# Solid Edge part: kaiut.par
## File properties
Author: Cymax
Template: Normal.par
Last saved by: Cymax
Revision: 24
Application: Solid Edge
Accuracy: 0,990
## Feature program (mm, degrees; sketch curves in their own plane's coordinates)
sketch for "unnamed Protrusion 1" plane through (0, 0, 0) normal (1, 0, 0) x-axis (0, 1, 0)
  arc centre (0, 1288.5152) radius 1839.926 from (-720.5308, -404.4594) to (720.5308, -404.4594) ccw
  line (720.5308, 0) -> (720.5308, -404.4594)
  line (-720.5308, 0) -> (720.5308, 0)
  line (-720.5308, -404.4594) -> (-720.5308, 0)
extrude "unnamed Protrusion 1" add finite 3507.3272 symmetric
sketch for "ExtrudedCutout_7" plane through (0, 0, 0) normal (0, 0, 1) x-axis (1, 0, 0)
  circle centre (-1600, 600) radius 75
extrude "ExtrudedCutout_7" cut finite 100 along -normal
mirror "unnamed Mirror 1" of "ExtrudedCutout_7" about plane through (0, 0, 0) normal (1, 0, 0)
extrude "unnamed Cutout 1" cut finite 100
mirror "unnamed Mirror 2" of "ExtrudedCutout_7", "unnamed Mirror 1" about plane through (0, 0, 0) normal (0, -1, 0)
extrude "unnamed Cutout 2" cut finite 100
extrude "unnamed Cutout 3" cut finite 100
draft "Draft_3"  Angles1 = 10 deg
thinwall "Thinwall_9"  Thickness = 100 mm
sketch for "ExtrudedCutout_12" plane through (-1618.0774, 0, -193.0702) normal (0.984808, 0, 0.173648) x-axis (0, 1, 0)
  line (-185, 196.0486) -> (-185, 1.9564)
  arc centre (-0.7454, 124.9335) radius 221.5245 from (-185, 1.9564) to (185, 4.22) ccw
  line (185, 4.22) -> (185, 196.0486)
extrude "ExtrudedCutout_12" cut finite 276.7398 along -normal
sketch for "unnamed RevolvedCutout 1" #1 plane through (0, -682.1712, -217.5478) normal (0, -0.984808, -0.173648) x-axis (-1, 0, 0)
  arc centre (-1165.304, -97.898) radius 200 from (-1165.304, 102.102) to (-965.304, -97.898) cw
  line (-965.304, -97.898) -> (-965.304, -138.606)
  line (-965.304, -138.606) -> (-1415.304, -138.606)
  line (-1415.304, -138.606) -> (-1415.304, -97.898)
  arc centre (-1215.304, -97.898) radius 200 from (-1215.304, 102.102) to (-1415.304, -97.898) ccw
  line (-1215.304, 102.102) -> (-1165.304, 102.102)
sketch for "unnamed RevolvedCutout 1" #2 plane through (0, -682.1712, -217.5478) normal (0, -0.984808, -0.173648) x-axis (-1, 0, 0)
  line (-515.304, 102.102) -> (-465.304, 102.102)
  arc centre (-465.304, -97.898) radius 200 from (-265.304, -97.898) to (-465.304, 102.102) ccw
  line (-265.304, -97.898) -> (-265.304, -145.2967)
  line (-265.304, -145.2967) -> (-715.304, -145.2967)
  line (-715.304, -145.2967) -> (-715.304, -97.898)
  arc centre (-515.304, -97.898) radius 200 from (-715.304, -97.898) to (-515.304, 102.102) cw
revolve "unnamed RevolvedCutout 1" cut finite
mirror "unnamed Mirror 3" of "unnamed RevolvedCutout 1" about plane through (0, 0, 0) normal (1, 0, 0)
revolve "unnamed RevolvedCutout 2" cut finite 14 deg
mirror "unnamed Mirror 4" of "unnamed Mirror 3", "unnamed RevolvedCutout 1" about plane through (0, 0, 0) normal (0, -1, 0)
revolve "unnamed RevolvedCutout 3" cut finite 14 deg
revolve "unnamed RevolvedCutout 4" cut finite 14 deg
sketch for "ExtrudedCutout_13" plane through (0, 0, 0) normal (0, 0, 1) x-axis (1, 0, 0)
  circle centre (424.9793, 0) radius 75
extrude "ExtrudedCutout_13" cut finite 1310.2189 along -normal
cool vent "Vent_3"  RibThickness = 15 mm; RibDepth = 10 mm; RibExtend = 20 mm; SparThickness = 15 mm; SparOffset = 30 mm; SparDepth = 10 mm; SparExtend = 20 mm
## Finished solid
Body 1: solid body, 112 faces, 331 edges, 214 vertices.
  Faces by surface: plane 66, cylinder 30, torus 16
  Edges by curve: line 199, circle 102, intersection 18, ellipse 12
Bounding box of the edges (mm; curved faces can reach further): 3507.327 x 1441.062 x 551.411, from (-1753.6636, -720.5308, -551.4108) to (1753.6636, 720.5308, 0).
Cylindrical faces by radius (mm): R75 x5, R76.8306 x2, R175 x4, R221.5245 x1, R430.6294 x4, R437.3201 x4, R678.028 x8, R1739.926 x1, R1839.926 x1
Toroidal faces (ring radius, tube radius in mm): R478.028 r200 x16
Planar faces by outward normal: +x 12, +y 1, +z 5, -x 12, -y 1, -z 4, oblique 31
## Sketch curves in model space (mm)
line (1415.304, -782.1798, 349.6287) -> (265.304, -782.1798, 349.6287)
arc centre (1165.304, -699.1711, -121.1371) radius 200 from (1165.304, -664.4414, -318.0986) through (1019.8293, -675.3381, -256.3003) to (965.304, -699.1711, -121.1371)
line (965.304, -699.1711, -121.1371) -> (965.304, -706.2399, -81.0475)
line (965.304, -706.2399, -81.0475) -> (1415.304, -706.2399, -81.0475)
line (1415.304, -706.2399, -81.0475) -> (1415.304, -699.1711, -121.1371)
arc centre (1215.304, -699.1711, -121.1371) radius 200 from (1215.304, -664.4414, -318.0986) through (1360.7788, -675.3381, -256.3003) to (1415.304, -699.1711, -121.1371)
line (1215.304, -664.4414, -318.0986) -> (1165.304, -664.4414, -318.0986)
line (265.304, -707.4018, -74.4585) -> (715.304, -707.4018, -74.4585)
line (715.304, -707.4018, -74.4585) -> (715.304, -699.1711, -121.1371)
arc centre (515.304, -699.1711, -121.1371) radius 200 from (715.304, -699.1711, -121.1371) through (652.5524, -673.9096, -264.4017) to (515.304, -664.4414, -318.0986)
line (515.304, -664.4414, -318.0986) -> (465.304, -664.4414, -318.0986)
arc centre (465.304, -699.1711, -121.1371) radius 200 from (265.304, -699.1711, -121.1371) through (328.0557, -673.9096, -264.4017) to (465.304, -664.4414, -318.0986)
line (265.304, -699.1711, -121.1371) -> (265.304, -707.4018, -74.4585)
circle centre (-1600, 600, 0) radius 75
line (0, 720.5308, 0) -> (0, 720.5308, -404.4594)
arc centre (0, 0, 1288.5152) radius 1839.926 from (0, -720.5308, -404.4594) through (0, 0, -551.4108) to (0, 720.5308, -404.4594)
line (0, -720.5308, -404.4594) -> (0, -720.5308, 0)
line (0, -720.5308, 0) -> (0, 720.5308, 0)
line (-66.6588, 684.428, -204.7493) -> (66.6588, 684.428, -204.7493)
line (-87.3789, 695.5691, -141.5648) -> (87.3789, 695.5691, -141.5648)
line (-94.0231, 701.7982, -106.2377) -> (94.0231, 701.7982, -106.2377)
line (-21.1483, 679.5591, -232.3621) -> (-21.1483, 707.4018, -74.4585)
line (19.6142, 707.4018, -74.4585) -> (19.6142, 679.5088, -232.6475)
line (-63.2284, 707.4018, -74.4585) -> (-63.2284, 683.718, -208.7759)
line (61.0355, 707.4018, -74.4585) -> (61.0355, 683.3122, -211.077)
line (100, 707.4018, -74.4585) -> (81.666, 690.2131, -171.9401)
line (-100, 707.4018, -74.4585) -> (-81.666, 690.2131, -171.9401)
line (-100, 707.4018, -74.4585) -> (100, 707.4018, -74.4585)
arc centre (6.1202, 692.6429, -158.1602) radius 76.8306 from (81.666, 690.2131, -171.9401) through (51.0491, 681.8204, -219.5378) to (0, 679.3438, -233.5831)
arc centre (-6.1202, 692.6429, -158.1602) radius 76.8306 from (-81.666, 690.2131, -171.9401) through (-51.0491, 681.8204, -219.5378) to (0, 679.3438, -233.5831)
line (-81.666, 690.2131, -171.9401) -> (81.666, 690.2131, -171.9401)
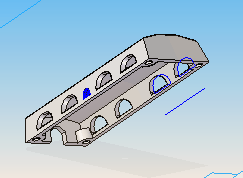
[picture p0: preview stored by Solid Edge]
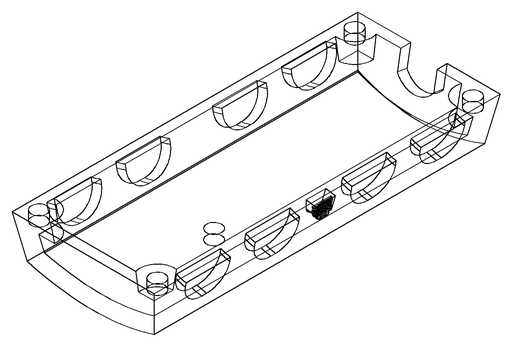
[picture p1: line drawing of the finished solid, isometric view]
